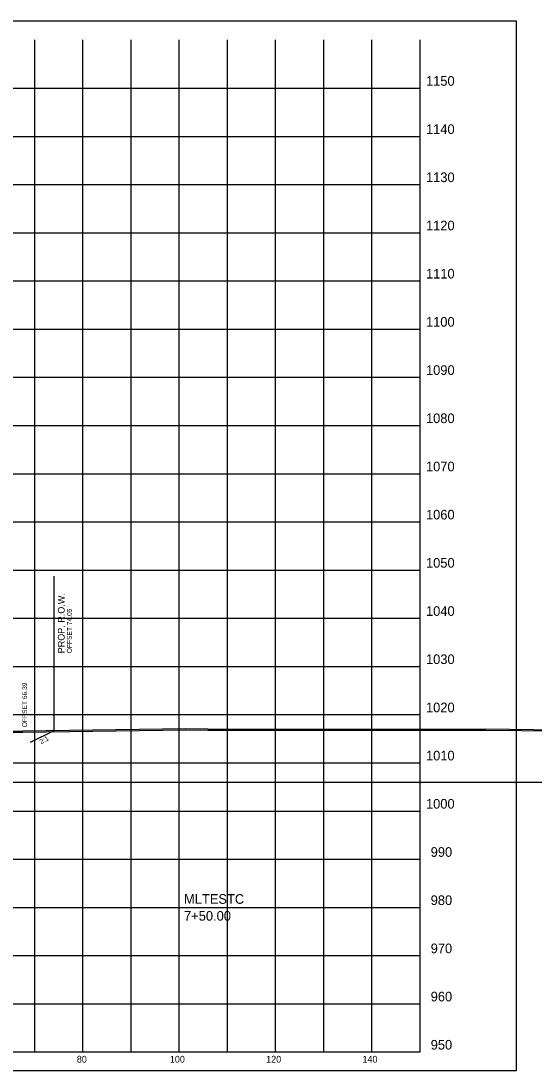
# Model space of a CAD drawing. Extents: x 1131015 to 1136271, y 133453 to 174329.
# Drawn here: x 1131407.6 to 1131514.1, y 156607.7 to 156825.6 of the extents above; entities that cross this region are included whole.
import ezdxf

# ---------------------------------------------------------------- set-up
doc = ezdxf.new("R2010")
doc.units = 0
for name, color, linetype in [('DESIGN - ROW - Right-of-Way and Easement Labels', 7, 'Continuous'), ('DESIGN - ROW - Right-of-Way Linework', 7, 'Continuous'), ('DESIGN - SCRATCH - User 1', 7, 'Continuous'), ('DESIGN - SHEET - Corner Text', 7, 'Continuous'), ('DESIGN - SHEET - Light Grid', 7, 'Continuous'), ('DESIGN - SHEET - Linework', 7, 'Continuous'), ('DESIGN - SHEET - Plot Shape', 7, 'Continuous'), ('DESIGN - TYPICAL - Slope Tie Text', 7, 'Continuous'), ('DESIGN - TYPICAL - Warning Text', 7, 'Continuous'), ('SURVEY - GROUND - Bottom of Topsoil Layer', 7, 'Continuous'), ('SURVEY - GROUND - Top of Ground', 7, 'Continuous')]:
    doc.layers.add(name, color=color, linetype=linetype)

msp = doc.modelspace()

# ---------------------------------------------------------------- linework, layer by layer
at = {"layer": 'DESIGN - ROW - Right-of-Way Linework'}
msp.add_line((1131414.51, 156678.39), (1131414.51, 156710.39), dxfattribs=at)
at = {"layer": 'DESIGN - SCRATCH - User 1'}
msp.add_line((1131409.57, 156675.92), (1131414.51, 156678.39), dxfattribs=at)
at = {"layer": 'DESIGN - SHEET - Light Grid'}
msp.add_line((1131340.46, 156667.66), (1131640.46, 156667.66), dxfattribs=at)
at = {"layer": 'DESIGN - SHEET - Linework'}
for p, q in [((1131410.46, 156611.66), (1131410.46, 156821.66)), ((1131420.46, 156611.66), (1131420.46, 156821.66)), ((1131430.46, 156611.66), (1131430.46, 156821.66)), ((1131440.46, 156611.66), (1131440.46, 156821.66)), ((1131450.46, 156611.66), (1131450.46, 156821.66)), ((1131460.46, 156611.66), (1131460.46, 156821.66)), ((1131470.46, 156611.66), (1131470.46, 156821.66)), ((1131480.46, 156611.66), (1131480.46, 156821.66)), ((1131190.46, 156811.66), (1131490.46, 156811.66)), ((1131190.46, 156801.66), (1131490.46, 156801.66)), ((1131190.46, 156791.66), (1131490.46, 156791.66)), ((1131190.46, 156781.66), (1131490.46, 156781.66)), ((1131190.46, 156771.66), (1131490.46, 156771.66)), ((1131190.46, 156761.66), (1131490.46, 156761.66)), ((1131190.46, 156751.66), (1131490.46, 156751.66)), ((1131190.46, 156741.66), (1131490.46, 156741.66)), ((1131190.46, 156731.66), (1131490.46, 156731.66)), ((1131190.46, 156721.66), (1131490.46, 156721.66)), ((1131190.46, 156711.66), (1131490.46, 156711.66)), ((1131190.46, 156701.66), (1131490.46, 156701.66)), ((1131190.46, 156691.66), (1131490.46, 156691.66)), ((1131190.46, 156681.66), (1131490.46, 156681.66)), ((1131190.46, 156671.66), (1131490.46, 156671.66)), ((1131190.46, 156661.66), (1131490.46, 156661.66)), ((1131190.46, 156651.66), (1131490.46, 156651.66)), ((1131190.46, 156641.66), (1131490.46, 156641.66)), ((1131190.46, 156631.66), (1131490.46, 156631.66)), ((1131190.46, 156621.66), (1131490.46, 156621.66))]:
    msp.add_line(p, q, dxfattribs=at)
msp.add_lwpolyline([(1131190.46, 156821.66), (1131190.46, 156611.66), (1131490.46, 156611.66), (1131490.46, 156821.66)], dxfattribs=at)
at = {"layer": 'DESIGN - SHEET - Plot Shape'}
msp.add_lwpolyline([(1131170.46, 156825.6), (1131510.46, 156825.6), (1131510.46, 156607.72), (1131170.46, 156607.72)], close=True, dxfattribs=at)
at = {"layer": 'SURVEY - GROUND - Bottom of Topsoil Layer'}
for p, q in [((1131392.87, 156677.94), (1131407.99, 156678.05)), ((1131407.99, 156678.05), (1131441.84, 156678.51)), ((1131441.84, 156678.51), (1131446.38, 156678.45)), ((1131446.38, 156678.45), (1131479.82, 156678.43)), ((1131479.82, 156678.43), (1131504.04, 156678.44)), ((1131504.04, 156678.44), (1131521.23, 156678.27))]:
    msp.add_line(p, q, dxfattribs=at)
at = {"layer": 'SURVEY - GROUND - Top of Ground'}
for p, q in [((1131392.87, 156678.19), (1131407.99, 156678.3)), ((1131407.99, 156678.3), (1131441.84, 156678.76)), ((1131441.84, 156678.76), (1131446.38, 156678.7)), ((1131446.38, 156678.7), (1131479.82, 156678.68)), ((1131479.82, 156678.68), (1131504.04, 156678.69)), ((1131504.04, 156678.69), (1131521.23, 156678.52))]:
    msp.add_line(p, q, dxfattribs=at)

# ---------------------------------------------------------------- texts
at = {"layer": 'DESIGN - ROW - Right-of-Way and Easement Labels'}
for s, height, p in [('PROP. R.O.W.', 1.4, (1131416.66, 156694.39)), ('OFFSET 74.05', 1, (1131418.16, 156694.39))]:
    msp.add_text(s, height=height, rotation=90, dxfattribs=at).set_placement(p)
at = {"layer": 'DESIGN - SCRATCH - User 1'}
msp.add_text('2:1', height=1, rotation=28.1289, dxfattribs=at).set_placement((1131411.8, 156675.52))
at = {"layer": 'DESIGN - SHEET - Corner Text'}
for s, height, p in [('1150', 2, (1131491.7, 156812.16)), ('1140', 2, (1131491.7, 156802.16)), ('1130', 2, (1131491.7, 156792.16)), ('1120', 2, (1131491.7, 156782.16)), ('1110', 2, (1131491.7, 156772.16)), ('1100', 2, (1131491.7, 156762.16)), ('1090', 2, (1131491.7, 156752.16)), ('1080', 2, (1131491.7, 156742.16)), ('1070', 2, (1131491.7, 156732.16)), ('1060', 2, (1131491.7, 156722.16)), ('1050', 2, (1131491.7, 156712.16)), ('1040', 2, (1131491.7, 156702.16)), ('1030', 2, (1131491.7, 156692.16)), ('1020', 2, (1131491.7, 156682.16)), ('1010', 2, (1131491.7, 156672.16)), ('1000', 2, (1131491.7, 156662.16)), ('990', 2, (1131492.68, 156652.16)), ('980', 2, (1131492.68, 156642.16)), ('970', 2, (1131492.68, 156632.16)), ('960', 2, (1131492.68, 156622.16)), ('950', 2, (1131492.68, 156612.16)), ('80', 1.4, (1131419.19, 156609.46)), ('100', 1.4, (1131438.51, 156609.46)), ('120', 1.4, (1131458.51, 156609.46)), ('140', 1.4, (1131478.51, 156609.46))]:
    msp.add_text(s, height=height, dxfattribs=at).set_placement(p)
at = {"layer": 'DESIGN - TYPICAL - Slope Tie Text'}
msp.add_text('OFFSET 66.39', height=1, rotation=90, dxfattribs=at).set_placement((1131408.85, 156679.04))
at = {"layer": 'DESIGN - TYPICAL - Warning Text'}
for s, p in [('MLTESTC', (1131441.46, 156642.41)), ('7+50.00', (1131441.46, 156638.91))]:
    msp.add_text(s, height=2, dxfattribs=at).set_placement(p)

doc.saveas('drawing.dxf')
